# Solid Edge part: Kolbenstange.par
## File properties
Last saved by: ahadarics
Revision: 76
Dokumentum tartalom típus: 0
Sűrűség: 0,000 kg/m^3
Pontosság: 0,990
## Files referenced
..\REMV 25_10.asm
\\Fsrv2\user\tervezes\Solid Edge ST4\Zylinder\Hengermodellek 2024\Körprofil R\REMV\REMV 25_10\Kit_1.par
rprofil R\REMV\REMV 25_10\Kit_1.par
rprofil R\REMV\REMV 25_10\REMV 25_10.asm
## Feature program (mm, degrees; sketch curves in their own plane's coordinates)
base feature "unnamed BaseFeature 1"
sketch for "unnamed Protrusion 1" plane through (89.5, 0, 0) normal (1, 0, 0) x-axis (0, 1, 0)
  circle centre (0, 0) radius 12.5
extrude "unnamed Protrusion 1" add to key point along -normal
thread "unnamed Thread 1"
chamfer "Letörés_1" setback 0.7
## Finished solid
Body 1: solid body, 13 faces, 23 edges, 12 vertices.
  Faces by surface: plane 9, cylinder 3, cone 1
  Edges by curve: line 12, circle 11
Bounding box of the edges (mm): 136.500 x 25.000 x 25.000, from (-47, -12.5, -12.5) to (89.5, 12.5, 12.5).
Cylindrical faces by radius (mm): R5 x2, R12.5 x1
Conical faces (half-angle, radius in mm at the cone's reference point): 45 deg R4.3 x1
Planar faces by outward normal: +x 3, +z 1, -x 4, -z 1
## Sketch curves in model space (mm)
circle centre (89.5, 0, 0) radius 12.5
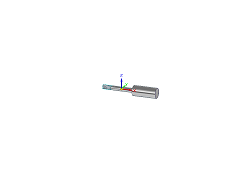
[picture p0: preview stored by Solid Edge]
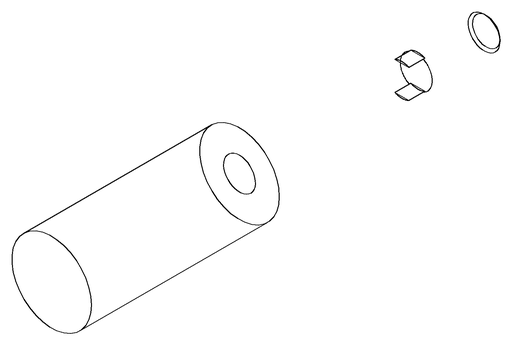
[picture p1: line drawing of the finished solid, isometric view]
